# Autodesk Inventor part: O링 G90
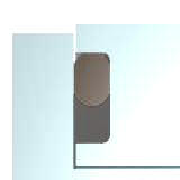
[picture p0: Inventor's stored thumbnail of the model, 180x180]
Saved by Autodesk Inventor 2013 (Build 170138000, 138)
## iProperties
IsCustomPart: 1
Created: 2012-02
Part Number: O링 G90
Material: 고무
Description: O-링
Document SubType Name: Modeling
Standard: JIS B 2406
Designer: mdu-01
Standards Organization: JIS
Language: ko-KR
Size Designation: G 90
Categories: <MemberInstance><Categories><Category DisplayName="샤프트 부품" InternalName="7f7aeb1f-a693-4053-b835-cee3144e0d98" Mnemonic="SHFT"><Category DisplayName="실링" Intern
Density: 0.93 g/cm^3
Author: mdu-01
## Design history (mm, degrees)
revolve "본체" stored, may be unused: angle "d7" = 90 deg
body "Solid1"
sketch "스케치1"
  geometry: L1 (0, 45.95)-(-1.2, 45.95); L2 (-1.2, 45.95)-(-1.2, 44.4); L3 (0, 44.969)-(0, 45.95); L4 (-1.2, 45.95)-(-1.2, 47.5); L5 (0, 46.931)-(0, 45.95) reference; L6 (-2.4, 46.931)-(-2.4, 45.95); L7 (-2.4, 44.969)-(-2.4, 45.95); L8 (-1.2, 45.95)-(-1.2, 47.5); L9 (0, 17.106)-(0, -2.851) reference; L10 (-2, 0)-(1, 0) reference; L11 (-2.62, 0)-(1.603, 0) reference; A1 r 1.55 centre (-1.2, 45.95) between (-1.2, 44.4) and (0, 44.969); A2 r 1.55 centre (-1.2, 45.95) between (0, 46.931) and (-1.2, 47.5); A3 r 1.55 centre (-1.2, 45.95) between (-1.2, 47.5) and (-2.4, 46.931); A4 r 1.55 centre (-1.2, 45.95) between (-2.4, 44.969) and (-1.2, 44.4)
  constraints: 18 end point, 8 point on circle, 5 symmetric about line, 4 centre point, 2 horizontal, 2 perpendicular, 1 parallel, 1 vertical, 9 other
  dimensions: "d0" = 1.55 radius of A1 (= 0.5 x QDM); "d1" = 1.2 distance between parallel lines of L9 L2 (= 0.5 x NTOR); "d2" = 95 diameter of L4.end L10 (= NDO1)
other parameters: "QDM" = 3.1 [user parameter; used in 1 equation term], "NTOR" = 2.4 [user parameter; used in 1 equation term], "NDO1" = 95 [user parameter; used in 1 equation term], "d3" = 0, "d4" = 0, "d5" = 0, "R2" = 0.2 [user parameter], "SD1" = 89.4 [user parameter], "R1" = 0.7 [user parameter], "NB1" = 4.1 [user parameter]
